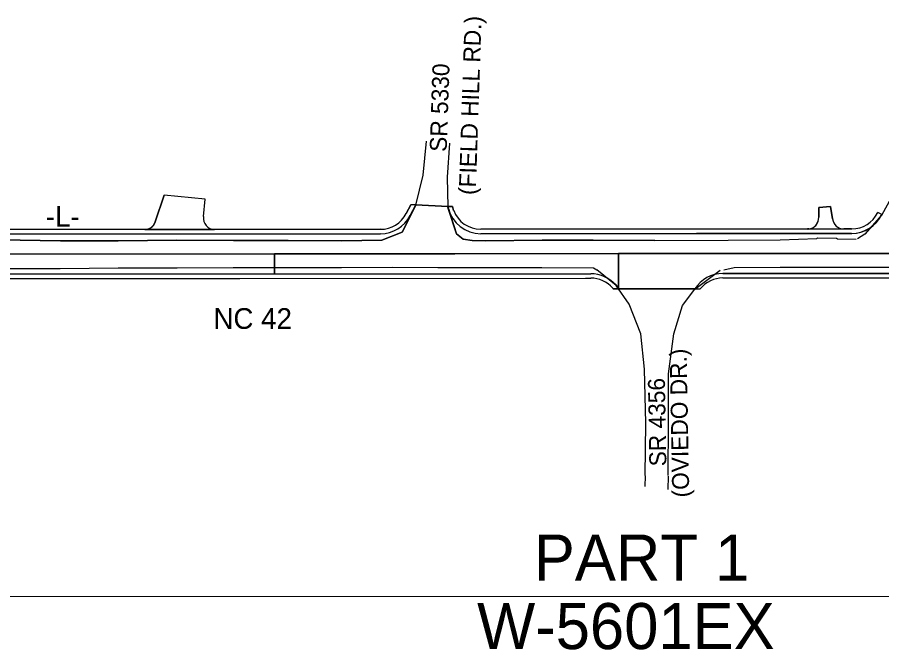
# Model space of a CAD drawing. Extents: x 2105791 to 2114488, y 667759 to 673441.
# Drawn here: x 2111121 to 2112480, y 669916 to 670911 of the extents above; entities that cross this region are included whole.
import ezdxf

# ---------------------------------------------------------------- set-up
doc = ezdxf.new("R2010")
doc.units = 0
for name, color, linetype in [('Exist Roads EOP', 7, 'Continuous'), ('Old_Level_1', 7, 'Continuous'), ('Prop Conc Driveway', 7, 'Continuous'), ('Prop EOT', 7, 'Continuous'), ('Prop Horizontal Alignment', 7, 'Continuous'), ('Prop Paved Shoulder', 7, 'Continuous'), ('Prop Shade Light', 7, 'Continuous')]:
    doc.layers.add(name, color=color, linetype=linetype)

msp = doc.modelspace()

# ---------------------------------------------------------------- linework, layer by layer
at = {"layer": 'Exist Roads EOP'}
for p, q in [((2112107.9, 670189.9), (2112107.3, 670173)), ((2112143.8, 670189.4), (2112143.2, 670168.2))]:
    msp.add_line(p, q, dxfattribs=at)
for points in [[(2112536.4, 670730.3), (2112508.8, 670655.5), (2112496.3, 670630.7), (2112479.7, 670600.3), (2112453, 670569.7), (2112441.5, 670562.4)], [(2111092.6, 670560.9), (2111188.6, 670559.5), (2111279, 670559.6), (2111371.4, 670560.4), (2111460.5, 670560), (2111546.7, 670560), (2111630.7, 670559.7), (2111693.7, 670560.6), (2111725.5, 670573.3), (2111747.1, 670615.7), (2111758.9, 670662.8), (2111764, 670716.2)], [(2111800.1, 670713.2), (2111796.2, 670659.4), (2111797.3, 670612.9), (2111810.9, 670570.7), (2111821.4, 670562.2), (2111835.9, 670560.1), (2111857.1, 670559.7), (2111945.7, 670560.4), (2112026, 670560.3), (2112122.8, 670560.1)], [(2112122.8, 670560.1), (2112238.1, 670560.6), (2112319.9, 670561.1), (2112377.4, 670563), (2112378.7, 670564.1), (2112408.6, 670563.9), (2112410, 670562.7), (2112439.5, 670562.2)], [(2110253.8, 670479.7), (2110323.2, 670485.3), (2110404.9, 670491.1), (2110498.2, 670497.3), (2110586, 670502.3), (2110678.1, 670507.3), (2110764.9, 670510.4), (2110854.2, 670512.7), (2110953, 670515.3), (2111054.7, 670516), (2111093.5, 670515.8), (2111187.9, 670516.2), (2111279.2, 670517.2), (2111371.8, 670516.9), (2111460.1, 670517.4), (2111546.7, 670517.5), (2111630.3, 670517.6), (2111711.2, 670518.1), (2111781.8, 670517.6), (2111857.4, 670517.7), (2111945.4, 670517.6), (2112026.4, 670517), (2112031.5, 670513.6)], [(2112231.2, 670513.9), (2112247.6, 670517.7), (2112319.8, 670518.2), (2112407.4, 670518.2), (2112504.5, 670518.1), (2112557.4, 670518.5), (2112646.7, 670518.4), (2112737.6, 670518.2), (2112825.3, 670518.2), (2112919.3, 670518.2), (2113021.3, 670518), (2113096.8, 670517.9), (2113173.1, 670517.7)], [(2112107.9, 670190.2), (2112108.9, 670272.9), (2112106.7, 670357.4), (2112101, 670413.3), (2112082.5, 670460), (2112062.1, 670489), (2112031.5, 670513.6)], [(2112144, 670190.3), (2112144.6, 670274.2), (2112144.3, 670350.1), (2112152.7, 670413.2), (2112166.5, 670457.6), (2112186, 670483.4), (2112225.8, 670513.4)]]:
    msp.add_lwpolyline(points, dxfattribs=at)
at = {"layer": 'Old_Level_1'}
msp.add_line((2110252.1, 670000.6), (2113812.4, 670000), dxfattribs=at)
at = {"layer": 'Prop Conc Driveway'}
for p, q in [((2112380.7, 670611.8), (2112399, 670613.7)), ((2112399, 670613.7), (2112402.3, 670594)), ((2112380.5, 670596.7), (2112380.7, 670611.8)), ((2112363.2, 670578), (2112419.8, 670578.1))]:
    msp.add_line(p, q, dxfattribs=at)
for centre, start, end in [((2112363, 670595.5), 270.5399, 4.4166), ((2112419.8, 670595.6), 185.7298, 270.0458)]:
    msp.add_arc(centre, 17.5, start, end, dxfattribs=at)
at = {"layer": 'Prop EOT'}
for p, q in [((2111337.6, 670589.4), (2111351.3, 670631.4)), ((2111416.1, 670624.8), (2111351.3, 670631.4)), ((2111413.3, 670597.5), (2111416.1, 670624.8)), ((2111738.3, 670599.3), (2111746.9, 670616.2)), ((2111746.9, 670616.2), (2111797.2, 670613.3)), ((2111798.2, 670610.5), (2111797.2, 670613.3)), ((2111105.8, 670570.1), (2111691.5, 670570.6)), ((2111849.2, 670570.7), (2112432.3, 670571.2)), ((2111105.8, 670507.1), (2112022.1, 670507.8)), ((2112229.9, 670508), (2113182.4, 670508.8)), ((2112061.9, 670489.5), (2112066, 670483.8)), ((2112185.8, 670483.9), (2112066, 670483.8))]:
    msp.add_line(p, q, dxfattribs=at)
for centre, radius, start, end in [((2111691.5, 670623.1), 52.5, 270.0458, 333.0447), ((2111849.2, 670623.2), 52.5, 193.9732, 270.0458), ((2112432.3, 670623.7), 52.5, 270.0459, 334.1502), ((2111321, 670594.8), 17.5, 270.0458, 351.4174), ((2111430.6, 670594.9), 17.5, 171.4174, 270.0458), ((2112022.1, 670455.3), 52.5, 40.6547, 90.0458), ((2112229.9, 670455.5), 52.5, 90.0458, 147.2037)]:
    msp.add_arc(centre, radius, start, end, dxfattribs=at)
at = {"layer": 'Prop Horizontal Alignment'}
msp.add_line((2111105.8, 670538.6), (2114200.2, 670541.1), dxfattribs=at)
at = {"layer": 'Prop Paved Shoulder'}
for p, q in [((2111732.1, 670602.4), (2111739.1, 670616.2)), ((2111746.9, 670616.2), (2111739.1, 670616.2)), ((2111797.2, 670613.4), (2111804.6, 670613.4)), ((2111804.6, 670613.4), (2111806.6, 670607)), ((2112479.5, 670600.8), (2112473.2, 670603.8)), ((2111105.8, 670577.1), (2111691.5, 670577.6)), ((2111849.2, 670577.7), (2112362.7, 670578.1)), ((2112419.8, 670578.1), (2112432.3, 670578.2)), ((2111105.9, 670500.1), (2112022.1, 670500.8)), ((2112229.9, 670501), (2113812.4, 670502.3)), ((2112057.6, 670483.8), (2112056.6, 670485)), ((2112066, 670483.8), (2112057.6, 670483.8)), ((2112185.8, 670483.9), (2112194.4, 670483.9))]:
    msp.add_line(p, q, dxfattribs=at)
for centre, start, end in [((2111691.5, 670623.1), 270.0458, 333.0447), ((2111849.2, 670623.2), 200.8077, 270.0458), ((2112432.3, 670623.7), 270.0459, 334.1502), ((2112022.1, 670455.3), 40.6547, 90.0458), ((2112229.9, 670455.5), 90.0458, 141.3078)]:
    msp.add_arc(centre, 45.5, start, end, dxfattribs=at)
at = {"layer": 'Prop Shade Light'}
for p, q in [((2111351.3, 670631.4), (2111337.6, 670589.4)), ((2111351.3, 670631.4), (2111337.6, 670589.4)), ((2111416.1, 670624.8), (2111351.3, 670631.4)), ((2111416.1, 670624.8), (2111351.3, 670631.4)), ((2111413.3, 670597.5), (2111416.1, 670624.8)), ((2111413.3, 670597.5), (2111416.1, 670624.8)), ((2111725.5, 670573.3), (2111747.1, 670615.7)), ((2111725.5, 670573.3), (2111747.1, 670615.7)), ((2111739.1, 670616.2), (2111732.1, 670602.4)), ((2111739.1, 670616.2), (2111732.1, 670602.4)), ((2111738.3, 670599.3), (2111746.9, 670616.2)), ((2111746.9, 670616.2), (2111738.3, 670599.3)), ((2111738.3, 670599.3), (2111746.9, 670616.2)), ((2111746.9, 670616.2), (2111738.3, 670599.3)), ((2111746.9, 670616.2), (2111739.1, 670616.2)), ((2111746.9, 670616.2), (2111739.1, 670616.2)), ((2111747.2, 670616.2), (2111746.9, 670616.2)), ((2111747.2, 670616.2), (2111746.9, 670616.2)), ((2111747.1, 670615.7), (2111747.2, 670616.2)), ((2111747.1, 670615.7), (2111747.2, 670616.2)), ((2111797.2, 670613.4), (2111747.2, 670616.2)), ((2111797.2, 670613.4), (2111747.2, 670616.2)), ((2111797.2, 670613.4), (2111797.2, 670613.3)), ((2111804.6, 670613.4), (2111797.2, 670613.4)), ((2111797.2, 670613.4), (2111797.2, 670613.3)), ((2111797.3, 670613), (2111797.2, 670613.4)), ((2111797.2, 670613.4), (2111797.2, 670613.3)), ((2111804.6, 670613.4), (2111797.2, 670613.4)), ((2111797.2, 670613.4), (2111797.2, 670613.3)), ((2111797.3, 670613), (2111797.2, 670613.4)), ((2111797.2, 670613.3), (2111798.2, 670610.5)), ((2111797.2, 670613.3), (2111798.2, 670610.5)), ((2111806.6, 670607), (2111804.6, 670613.4)), ((2111806.6, 670607), (2111804.6, 670613.4)), ((2112399, 670613.7), (2112380.7, 670611.8)), ((2112399, 670613.7), (2112380.7, 670611.8)), ((2112402.3, 670593.9), (2112399, 670613.7)), ((2112402.3, 670593.9), (2112399, 670613.7)), ((2111798.1, 670610.5), (2111810.9, 670570.7)), ((2111798.1, 670610.5), (2111810.9, 670570.7)), ((2112380.7, 670611.8), (2112380.5, 670596.9)), ((2112380.7, 670611.8), (2112380.5, 670596.9)), ((2112479.5, 670600.8), (2112473.2, 670603.8)), ((2112479.5, 670600.8), (2112473.2, 670603.8)), ((2111321, 670577.3), (2111105.8, 670577.1)), ((2111321, 670577.3), (2111105.8, 670577.1)), ((2111321, 670577.3), (2111430.6, 670577.4)), ((2111430.6, 670577.4), (2111321, 670577.3)), ((2111321, 670577.3), (2111430.6, 670577.4)), ((2111430.6, 670577.4), (2111321, 670577.3)), ((2111691.5, 670577.6), (2111430.6, 670577.4)), ((2111691.5, 670577.6), (2111430.6, 670577.4)), ((2112362.7, 670578.1), (2111849.2, 670577.7)), ((2112362.7, 670578.1), (2111849.2, 670577.7)), ((2112362.7, 670578.1), (2112419.8, 670578.1)), ((2112364.9, 670578.1), (2112362.7, 670578.1)), ((2112362.7, 670578.1), (2112419.8, 670578.1)), ((2112364.9, 670578.1), (2112362.7, 670578.1)), ((2112419.8, 670578.1), (2112363.2, 670578)), ((2112419.8, 670578.1), (2112363.2, 670578)), ((2112364.9, 670578.1), (2112419.8, 670578.1)), ((2112364.9, 670578.1), (2112419.8, 670578.1)), ((2112432.3, 670578.2), (2112419.8, 670578.1)), ((2112432.3, 670578.2), (2112419.8, 670578.1)), ((2111105.8, 670570.1), (2111691.5, 670570.6)), ((2111691.5, 670570.6), (2111105.8, 670570.1)), ((2111105.8, 670570.1), (2111691.5, 670570.6)), ((2111691.5, 670570.6), (2111105.8, 670570.1)), ((2111810.9, 670570.7), (2111821.4, 670562.2)), ((2111810.9, 670570.7), (2111821.4, 670562.2)), ((2111821.4, 670562.2), (2111835.9, 670560.1)), ((2111821.4, 670562.2), (2111835.9, 670560.1)), ((2111835.9, 670560.1), (2111857.1, 670559.7)), ((2111835.9, 670560.1), (2111857.1, 670559.7)), ((2111849.2, 670570.7), (2112432.3, 670571.2)), ((2111849.2, 670570.7), (2112432.3, 670571.2)), ((2112188.2, 670571), (2111849.2, 670570.7)), ((2112188.2, 670571), (2111849.2, 670570.7)), ((2112026, 670560.3), (2112122.8, 670560.1)), ((2112026, 670560.3), (2112122.8, 670560.1)), ((2112432.3, 670571.2), (2112188.2, 670571)), ((2112432.3, 670571.2), (2112188.2, 670571)), ((2111524.9, 670538.9), (2111105.8, 670538.6)), ((2111105.8, 670538.6), (2111524.9, 670538.9)), ((2111524.9, 670538.9), (2111105.8, 670538.6)), ((2111105.8, 670538.6), (2111524.9, 670538.9)), ((2112065.9, 670539.4), (2111524.9, 670538.9)), ((2111524.9, 670538.9), (2112065.9, 670539.4)), ((2112065.9, 670539.4), (2111524.9, 670538.9)), ((2111524.9, 670538.9), (2112065.9, 670539.4)), ((2111524.9, 670538.9), (2111524.9, 670507.4)), ((2111524.9, 670507.4), (2111524.9, 670538.9)), ((2111524.9, 670538.9), (2111524.9, 670507.4)), ((2111524.9, 670507.4), (2111524.9, 670538.9)), ((2112537.1, 670539.7), (2112065.9, 670539.4)), ((2112065.9, 670539.4), (2112537.1, 670539.7)), ((2112537.1, 670539.7), (2112065.9, 670539.4)), ((2112065.9, 670539.4), (2112537.1, 670539.7)), ((2112065.9, 670539.4), (2112066, 670483.8)), ((2112066, 670483.8), (2112065.9, 670539.4)), ((2112065.9, 670539.4), (2112066, 670483.8)), ((2112066, 670483.8), (2112065.9, 670539.4)), ((2112022.1, 670507.8), (2111105.8, 670507.1)), ((2112022.1, 670507.8), (2111105.8, 670507.1)), ((2111105.8, 670507.1), (2111524.9, 670507.4)), ((2111105.8, 670507.1), (2111524.9, 670507.4)), ((2111524.9, 670507.4), (2112022.1, 670507.8)), ((2111524.9, 670507.4), (2112022.1, 670507.8)), ((2112537.1, 670508.2), (2112229.9, 670508)), ((2112229.9, 670508), (2112537.1, 670508.2)), ((2112537.1, 670508.2), (2112229.9, 670508)), ((2112229.9, 670508), (2112537.1, 670508.2)), ((2111089.7, 670500.1), (2111120.6, 670500.1)), ((2111089.7, 670500.1), (2111120.6, 670500.1)), ((2111105.9, 670500.1), (2111120.6, 670500.1)), ((2111105.9, 670500.1), (2111120.6, 670500.1)), ((2111120.6, 670500.1), (2111159.7, 670500.1)), ((2111120.6, 670500.1), (2111159.7, 670500.1)), ((2111120.6, 670500.1), (2111159.7, 670500.1)), ((2111120.6, 670500.1), (2111159.7, 670500.1)), ((2111159.7, 670500.1), (2111195.1, 670500.2)), ((2111159.7, 670500.1), (2111195.1, 670500.2)), ((2111159.7, 670500.1), (2111195.1, 670500.2)), ((2111159.7, 670500.1), (2111195.1, 670500.2)), ((2111195.1, 670500.2), (2111238.4, 670500.2)), ((2111195.1, 670500.2), (2111238.4, 670500.2)), ((2111238.4, 670500.2), (2111470.4, 670500.4)), ((2111238.4, 670500.2), (2111470.4, 670500.4)), ((2111470.4, 670500.4), (2112013.9, 670500.8)), ((2111470.4, 670500.4), (2112013.9, 670500.8)), ((2111470.4, 670500.4), (2112013.9, 670500.8)), ((2111470.4, 670500.4), (2112013.9, 670500.8)), ((2112013.9, 670500.8), (2112022.1, 670500.8)), ((2112013.9, 670500.8), (2112022.1, 670500.8)), ((2112013.9, 670500.8), (2112022.1, 670500.8)), ((2112013.9, 670500.8), (2112022.1, 670500.8)), ((2112229.9, 670501), (2112537.1, 670501.2)), ((2112229.9, 670501), (2112537.1, 670501.2)), ((2112056.6, 670485), (2112057.6, 670483.8)), ((2112056.6, 670485), (2112057.6, 670483.8)), ((2112057.6, 670483.8), (2112066, 670483.8)), ((2112057.6, 670483.8), (2112066, 670483.8)), ((2112066, 670483.8), (2112061.9, 670489.5)), ((2112061.9, 670489.5), (2112066, 670483.8)), ((2112066, 670483.8), (2112061.9, 670489.5)), ((2112061.9, 670489.5), (2112066, 670483.8)), ((2112066, 670483.8), (2112185.8, 670483.9)), ((2112066, 670483.8), (2112185.8, 670483.9)), ((2112185.8, 670483.9), (2112194.4, 670483.9)), ((2112185.8, 670483.9), (2112194.4, 670483.9))]:
    msp.add_line(p, q, dxfattribs=at)
for points in [[(2111747.2, 670616.2), (2111747.1, 670615.7), (2111725.5, 670573.3), (2111693.7, 670560.6), (2111630.7, 670559.7), (2111546.7, 670560), (2111460.5, 670560), (2111371.4, 670560.4), (2111279, 670559.6), (2111188.6, 670559.5), (2111092.6, 670560.9), (2111056.3, 670565.8), (2111037.6, 670569.8)], [(2111747.2, 670616.2), (2111747.1, 670615.7), (2111725.5, 670573.3), (2111693.7, 670560.6), (2111630.7, 670559.7), (2111546.7, 670560), (2111460.5, 670560), (2111371.4, 670560.4), (2111279, 670559.6), (2111188.6, 670559.5), (2111092.6, 670560.9), (2111056.3, 670565.8), (2111037.6, 670569.8)], [(2112122.8, 670560.1), (2112026, 670560.3), (2111945.7, 670560.4), (2111857.1, 670559.7), (2111835.9, 670560.1), (2111821.4, 670562.2), (2111810.9, 670570.7), (2111798.1, 670610.5), (2111797.3, 670612.9), (2111797.3, 670613)], [(2112122.8, 670560.1), (2112026, 670560.3), (2111945.7, 670560.4), (2111857.1, 670559.7), (2111835.9, 670560.1), (2111821.4, 670562.2), (2111810.9, 670570.7), (2111798.1, 670610.5), (2111797.3, 670612.9), (2111797.3, 670613)], [(2112491.1, 670621.3), (2112479.7, 670600.3), (2112478.7, 670599.2)], [(2112491.1, 670621.3), (2112479.7, 670600.3), (2112478.7, 670599.2)], [(2111798.2, 670610.5), (2111798.1, 670610.5)], [(2111798.2, 670610.5), (2111798.1, 670610.5)], [(2111188.6, 670559.5), (2111279, 670559.6), (2111371.4, 670560.4), (2111460.5, 670560), (2111546.7, 670560), (2111630.7, 670559.7), (2111693.7, 670560.6), (2111725.5, 670573.3)], [(2111188.6, 670559.5), (2111279, 670559.6), (2111371.4, 670560.4), (2111460.5, 670560), (2111546.7, 670560), (2111630.7, 670559.7), (2111693.7, 670560.6), (2111725.5, 670573.3)], [(2111037.6, 670569.8), (2111056.3, 670565.8), (2111092.6, 670560.9), (2111188.6, 670559.5)], [(2111037.6, 670569.8), (2111056.3, 670565.8), (2111092.6, 670560.9), (2111188.6, 670559.5)], [(2111857.1, 670559.7), (2111945.7, 670560.4), (2112026, 670560.3)], [(2111857.1, 670559.7), (2111945.7, 670560.4), (2112026, 670560.3)], [(2111195.1, 670500.2), (2111238.4, 670500.2), (2111470.4, 670500.4)], [(2111195.1, 670500.2), (2111238.4, 670500.2), (2111470.4, 670500.4)]]:
    msp.add_lwpolyline(points, dxfattribs=at)
for centre, radius, start, end in [((2111691.5, 670623.1), 45.5, 270.0458, 333.0447), ((2111691.5, 670623.1), 45.5, 270.0458, 333.0447), ((2111691.5, 670623.1), 52.5, 270.0458, 333.0447), ((2111691.5, 670623.1), 52.5, 270.0458, 333.0447), ((2111691.5, 670623.1), 52.5, 270.0458, 333.0447), ((2111691.5, 670623.1), 52.5, 270.0458, 333.0447), ((2111849.2, 670623.2), 52.5, 193.9732, 270.0458), ((2111849.2, 670623.2), 52.5, 193.9732, 270.0458), ((2111849.2, 670623.2), 52.5, 193.9732, 270.0458), ((2111849.2, 670623.2), 52.5, 193.9732, 270.0458), ((2111849.2, 670623.2), 45.5, 200.8077, 270.0458), ((2111849.2, 670623.2), 45.5, 200.8077, 270.0458), ((2112432.3, 670623.7), 45.5, 270.0459, 334.1502), ((2112432.3, 670623.7), 45.5, 270.0459, 334.1502), ((2112432.3, 670623.7), 52.5, 270.0459, 334.1502), ((2112432.3, 670623.7), 52.5, 270.0459, 334.1502), ((2112432.3, 670623.7), 52.5, 270.0459, 332.1764), ((2112432.3, 670623.7), 52.5, 270.0459, 332.1764), ((2111321, 670594.8), 17.5, 270.0458, 341.9812), ((2111321, 670594.8), 17.5, 270.0458, 341.9812), ((2111430.6, 670594.9), 17.5, 171.4174, 270.0458), ((2111430.6, 670594.9), 17.5, 171.4174, 270.0458), ((2112363, 670595.5), 17.5, 275.9782, 4.4166), ((2112363, 670595.5), 17.5, 275.9782, 4.4166), ((2112419.8, 670595.6), 17.5, 185.7298, 270.0458), ((2112419.8, 670595.6), 17.5, 185.7298, 270.0458), ((2112363, 670595.5), 17.5, 270.5399, 275.9782), ((2112363, 670595.5), 17.5, 270.5399, 275.9782), ((2112022.1, 670455.3), 52.5, 40.6547, 90.0458), ((2112022.1, 670455.3), 52.5, 40.6547, 90.0458), ((2112022.1, 670455.3), 52.5, 40.6547, 90.0458), ((2112022.1, 670455.3), 52.5, 40.6547, 90.0458), ((2112229.9, 670455.5), 52.5, 90.0458, 147.2037), ((2112229.9, 670455.5), 52.5, 90.0458, 147.2037), ((2112229.9, 670455.5), 52.5, 90.0458, 147.2037), ((2112229.9, 670455.5), 52.5, 90.0458, 147.2037), ((2112022.1, 670455.3), 45.5, 40.6547, 90.0458), ((2112022.1, 670455.3), 45.5, 40.6547, 90.0458), ((2112229.9, 670455.5), 45.5, 90.0458, 141.3078), ((2112229.9, 670455.5), 45.5, 90.0458, 141.3078)]:
    msp.add_arc(centre, radius, start, end, dxfattribs=at)

# ---------------------------------------------------------------- texts
at = {"layer": 'Old_Level_1'}
for s, height, rotation, p in [('(FIELD HILL RD.)', 26.696, 88.1043, (2111841.3, 670631.3)), ('SR 5330  ', 26.7, 88.1043, (2111795.6, 670699.1)), ('-L-', 32.55, 360, (2111165.5, 670581.7)), ('(OVIEDO DR.) ', 26.696, 91.0239, (2112177, 670156.1)), ('SR 4356 ', 26.7, 91.0239, (2112141.1, 670205)), ('W-5601EX', 72.35, 360, (2111843.5, 669917.3))]:
    msp.add_text(s, height=height, rotation=rotation, dxfattribs=at).set_placement(p)
for s, height, p in [('NC 42', 32.55, (2111429, 670421)), ('PART 1', 72.35, (2111932.6, 670025.1))]:
    msp.add_text(s, height=height, dxfattribs=at).set_placement(p)

doc.saveas('drawing.dxf')
